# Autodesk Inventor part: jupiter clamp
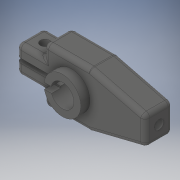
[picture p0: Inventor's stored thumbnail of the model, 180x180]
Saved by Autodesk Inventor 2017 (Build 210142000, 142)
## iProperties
Created: 2016-05
Part Number: jupiter clamp
Material: Generic
Document SubType Name: Modeling
Designer: Stan
Density: 1 g/cm^3
Appearance: Gray
Author: Stan
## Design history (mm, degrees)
sketch "Sketch1"
  geometry: L1 (-9.525, 9.525)-(6.35, 9.525); L2 (6.35, -9.463)-(-9.525, -9.463); L3 (25.4, 4.763)-(25.4, -4.763); L4 (25.4, -4.763)-(6.35, -9.463); L5 (25.4, 4.763)-(6.35, 9.525); L6 (-9.525, 9.525)-(-9.525, 4.763); L7 (-9.525, 4.763)-(-19.05, 4.762); L8 (-19.05, -4.7)-(-9.525, -4.7); L9 (-9.525, -4.7)-(-9.525, -9.463); L10 (-3.895, 0.762)-(-19.05, 0.762); L11 (-3.895, -0.762)-(-19.05, -0.762); L12 (-19.05, -4.7)-(-19.05, -0.762); L13 (-19.05, 0.762)-(-19.05, 4.762); A1 r 3.969 centre (0, 0) between (-3.895, -0.762) and (-3.895, 0.762); 1 further point
  constraints: 26 end point, 4 perpendicular, 2 point on circle, 2 point on line, 2 vertical, 1 centre point, 1 coincident, 1 horizontal, 1 parallel
  dimensions: "d1" = 9.525 distance from line of L1 point (0, 0); "d2" = 25.4 horizontal distance of L3.end point (0, 0); "d4" = 9.525 distance of L3.start L3.end; "d5" = 4.7625 vertical distance of point (0, 0) L3.start; "d7" = 7.9375 diameter of A1; "d8" = 19.05 horizontal distance of L8.start point (0, 0); "d11" = 9.525 distance from line of point (0, 0) L6; "d12" = 19.05 distance from line of point (0, 0) L13; "d14" = 1.524 distance between parallel lines of L11 L10; "d15" = 0.762 distance from line of L10 point (0, 0); "d16" = 15.875 distance of L1.start L1.end; "d17" = 15.875 distance of L2.start L2.end; "d18" = 4.7625 distance between parallel lines of L2 L8; "d19" = 4.7625 distance between parallel lines of L7 L1
extrude "Extrusion1" new body sketch "Sketch1" distance "d20" = 9.525; taper "d21" = 0 deg
fillet "Fillet1" dims "d22" = 1.5875
sketch "Sketch2"
  geometry: C1 r 1.587 at (3.175, 3.519); 1 further point
  constraints: 1 centre point
  dimensions: "d23" = 3.175 diameter of C1
extrude "Extrusion2" cut sketch "Sketch2" distance "d24" = 15.875; taper "d25" = 0 deg
sketch "Sketch3"
  geometry: L1 (-1.587, 6.35)-(-1.588, 0) reference; C1 r 1.587 at (3.492, 3.175); 1 further point
  constraints: 1 centre point
  dimensions: "d26" = 3.175 diameter of C1; "d27" = 5.08 distance from line of C1.centre L1
extrude "Extrusion3" cut sketch "Sketch3" distance "d28" = 9.525; taper "d29" = 0 deg
fillet "Fillet2" dims "d30" = 1.5875
fillet "Fillet3" dims "d31" = 1.5875
sketch "Sketch4"
  geometry: L1 (-3.895, 0.762)-(-6.304, 0.762); L2 (-17.462, 0.762)-(-3.895, 0.762) reference; L3 (-3.76, -1.27)-(-6.222, -1.27); A1 r 6.35 centre (0, 0) between (-6.222, -1.27) and (-6.304, 0.762); A2 r 3.969 centre (0, 0) between (-3.76, -1.27) and (-3.895, 0.762); 1 further point
  constraints: 5 end point, 4 point on circle, 2 centre point, 2 coincident, 1 parallel, 1 point on line
  dimensions: "d32" = 12.7 diameter of A1
extrude "Extrusion4" join sketch "Sketch4" distance "d33" = 3.175; taper "d34" = 0 deg
body "Solid1"
